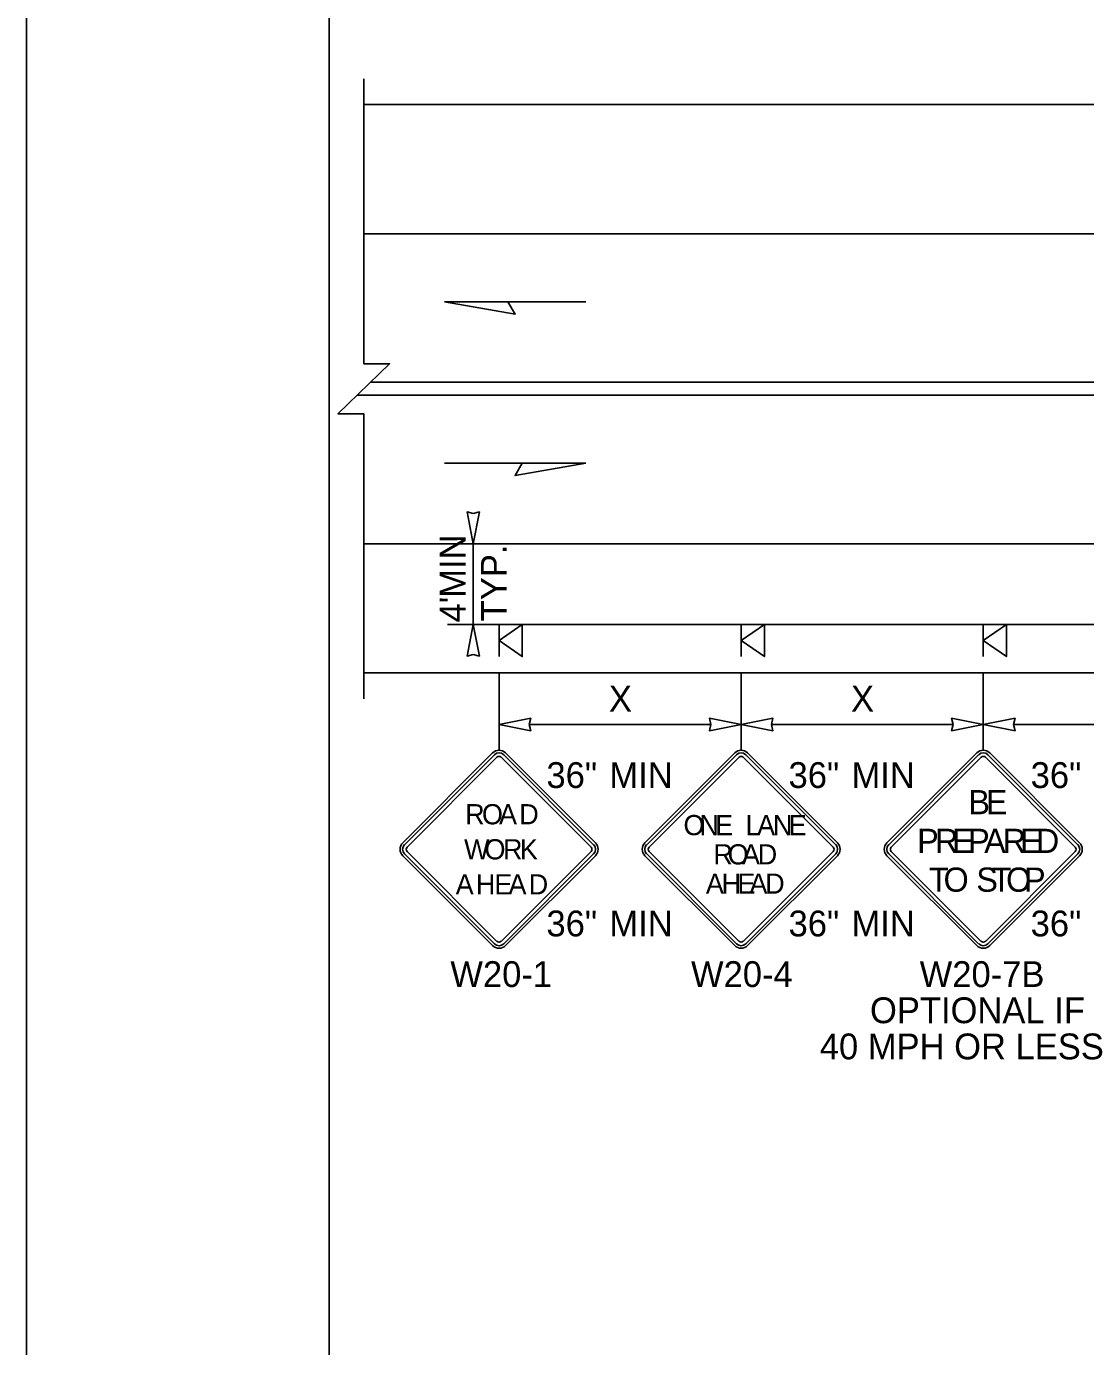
# Model space of a CAD drawing. Extents: x 99998.9 to 100095.7, y 99995 to 100010.7.
# Drawn here: x 100039.062 to 100042.344, y 100003.646 to 100007.734 of the extents above; entities that cross this region are included whole.
import ezdxf

# ---------------------------------------------------------------- set-up
doc = ezdxf.new("R2010")
doc.units = 0
for name, color, linetype in [('RD_ED_ShoulderPavedEdge', 7, 'Continuous'), ('RD_MK_LineDblYellowCenter', 7, 'Continuous'), ('RD_MK_LineEdgeWhite', 7, 'Continuous'), ('SH_GI_PlotLimits', 7, 'Continuous'), ('SH_GI_SheetBorder', 7, 'Continuous'), ('TR_SN_ConstructionSigns', 7, 'Continuous'), ('TR_WZ_PortableSignMountBlk-Org', 7, 'Continuous'), ('TR_WZ_WorkZoneDetails', 7, 'Continuous'), ('TR_WZ_WorkZoneTextCurrent', 7, 'Continuous')]:
    doc.layers.add(name, color=color, linetype=linetype)

msp = doc.modelspace()

# ---------------------------------------------------------------- linework, layer by layer
at = {"layer": 'RD_ED_ShoulderPavedEdge'}
for p, q in [((100040.1076, 100007.4923), (100055.6424, 100007.4923)), ((100040.1076, 100005.7323), (100055.6424, 100005.7323))]:
    msp.add_line(p, q, dxfattribs=at)
at = {"layer": 'RD_MK_LineDblYellowCenter'}
for p, q in [((100040.1282, 100006.6323), (100043.4767, 100006.6323)), ((100040.0869, 100006.5923), (100043.4767, 100006.5923))]:
    msp.add_line(p, q, dxfattribs=at)
at = {"layer": 'RD_MK_LineEdgeWhite'}
for p, q in [((100040.1076, 100007.0923), (100055.6424, 100007.0923)), ((100040.1076, 100006.1323), (100055.6424, 100006.1323))]:
    msp.add_line(p, q, dxfattribs=at)
at = {"layer": 'SH_GI_PlotLimits'}
msp.add_lwpolyline([(100039.0625, 99999.6875), (100056.0625, 99999.6875), (100056.0625, 100010.6875), (100039.0625, 100010.6875)], close=True, dxfattribs=at)
at = {"layer": 'SH_GI_SheetBorder'}
msp.add_line((100040, 100010.375), (100040, 100000), dxfattribs=at)
at = {"layer": 'TR_SN_ConstructionSigns'}
for p, q in [((100040.5068, 100005.4841), (100040.2283, 100005.2057)), ((100040.5123, 100005.4786), (100040.2339, 100005.2001)), ((100040.2416, 100005.1924), (100040.52, 100005.4708)), ((100040.5333, 100005.4708), (100040.8117, 100005.1924)), ((100040.8194, 100005.2001), (100040.541, 100005.4786)), ((100040.825, 100005.2057), (100040.5465, 100005.4841)), ((100041.2568, 100005.4841), (100040.9783, 100005.2057)), ((100041.2623, 100005.4786), (100040.9839, 100005.2001)), ((100040.9916, 100005.1924), (100041.27, 100005.4708)), ((100041.2833, 100005.4708), (100041.5617, 100005.1924)), ((100041.5694, 100005.2001), (100041.291, 100005.4786)), ((100041.575, 100005.2057), (100041.2965, 100005.4841)), ((100042.0068, 100005.4841), (100041.7283, 100005.2057)), ((100042.0123, 100005.4786), (100041.7339, 100005.2001)), ((100041.7416, 100005.1924), (100042.02, 100005.4708)), ((100042.0333, 100005.4708), (100042.3117, 100005.1924)), ((100042.3194, 100005.2001), (100042.041, 100005.4786)), ((100042.325, 100005.2057), (100042.0465, 100005.4841)), ((100040.52, 100004.9007), (100040.2416, 100005.1792)), ((100040.8117, 100005.1792), (100040.5333, 100004.9007)), ((100041.27, 100004.9007), (100040.9916, 100005.1792)), ((100041.5617, 100005.1792), (100041.2833, 100004.9007)), ((100042.02, 100004.9007), (100041.7416, 100005.1792)), ((100042.3117, 100005.1792), (100042.0333, 100004.9007)), ((100040.2283, 100005.1659), (100040.5068, 100004.8875)), ((100040.2339, 100005.1714), (100040.5123, 100004.893)), ((100040.541, 100004.893), (100040.8194, 100005.1714)), ((100040.5465, 100004.8875), (100040.825, 100005.1659)), ((100040.9783, 100005.1659), (100041.2568, 100004.8875)), ((100040.9839, 100005.1714), (100041.2623, 100004.893)), ((100041.291, 100004.893), (100041.5694, 100005.1714)), ((100041.2965, 100004.8875), (100041.575, 100005.1659)), ((100041.7283, 100005.1659), (100042.0068, 100004.8875)), ((100041.7339, 100005.1714), (100042.0123, 100004.893)), ((100042.041, 100004.893), (100042.3194, 100005.1714)), ((100042.0465, 100004.8875), (100042.325, 100005.1659))]:
    msp.add_line(p, q, dxfattribs=at)
for centre, radius, start, end in [((100040.5267, 100005.4642), 0.0281, 45, 135), ((100040.5267, 100005.4642), 0.0203, 45, 135), ((100040.5267, 100005.4642), 0.00937, 45, 135), ((100041.2767, 100005.4642), 0.0281, 45, 135), ((100041.2767, 100005.4642), 0.0203, 45, 135), ((100041.2767, 100005.4642), 0.00937, 45, 135), ((100042.0267, 100005.4642), 0.0281, 45, 135), ((100042.0267, 100005.4642), 0.0203, 45, 135), ((100042.0267, 100005.4642), 0.00937, 45, 135), ((100040.2482, 100005.1858), 0.0281, 135, 225), ((100040.2482, 100005.1858), 0.0203, 135, 225), ((100040.2482, 100005.1858), 0.00937, 135, 225), ((100040.8051, 100005.1858), 0.00937, 315, 45), ((100040.8051, 100005.1858), 0.0203, 315, 45), ((100040.8051, 100005.1858), 0.0281, 315, 45), ((100040.9982, 100005.1858), 0.0281, 135, 225), ((100040.9982, 100005.1858), 0.0203, 135, 225), ((100040.9982, 100005.1858), 0.00937, 135, 225), ((100041.5551, 100005.1858), 0.00937, 315, 45), ((100041.5551, 100005.1858), 0.0203, 315, 45), ((100041.5551, 100005.1858), 0.0281, 315, 45), ((100041.7482, 100005.1858), 0.0281, 135, 225), ((100041.7482, 100005.1858), 0.0203, 135, 225), ((100041.7482, 100005.1858), 0.00937, 135, 225), ((100042.3051, 100005.1858), 0.00937, 315, 45), ((100042.3051, 100005.1858), 0.0203, 315, 45), ((100042.3051, 100005.1858), 0.0281, 315, 45), ((100040.5267, 100004.9074), 0.0203, 225, 315), ((100040.5267, 100004.9074), 0.00937, 225, 315), ((100041.2767, 100004.9074), 0.0203, 225, 315), ((100041.2767, 100004.9074), 0.00937, 225, 315), ((100042.0267, 100004.9074), 0.0203, 225, 315), ((100042.0267, 100004.9074), 0.00937, 225, 315), ((100040.5267, 100004.9074), 0.0281, 225, 315), ((100041.2767, 100004.9074), 0.0281, 225, 315), ((100042.0267, 100004.9074), 0.0281, 225, 315)]:
    msp.add_arc(centre, radius, start, end, dxfattribs=at)
at = {"layer": 'TR_WZ_PortableSignMountBlk-Org'}
for p, q in [((100040.5267, 100005.7824), (100040.5267, 100005.8824)), ((100041.2767, 100005.7824), (100041.2767, 100005.8824)), ((100042.0267, 100005.7824), (100042.0267, 100005.8824))]:
    msp.add_line(p, q, dxfattribs=at)
for points in [[(100040.5267, 100005.8323), (100040.5985, 100005.8824), (100040.5985, 100005.7824)], [(100041.2767, 100005.8323), (100041.3485, 100005.8824), (100041.3485, 100005.7824)], [(100042.0267, 100005.8323), (100042.0985, 100005.8824), (100042.0985, 100005.7824)]]:
    msp.add_lwpolyline(points, close=True, dxfattribs=at)
at = {"layer": 'TR_WZ_WorkZoneDetails'}
for p, q in [((100040.5541, 100006.8816), (100040.7952, 100006.8816)), ((100040.5987, 100006.3816), (100040.3576, 100006.3816)), ((100040.3667, 100006.1323), (100040.5267, 100006.1323)), ((100040.4467, 100005.8824), (100040.4467, 100006.1323)), ((100040.3667, 100005.8824), (100040.5267, 100005.8824)), ((100040.5267, 100005.8824), (100043.5267, 100005.8824)), ((100040.5267, 100005.7326), (100040.5267, 100005.4923)), ((100041.2767, 100005.7323), (100041.2767, 100005.4923)), ((100042.0267, 100005.7323), (100042.0267, 100005.4923)), ((100041.1829, 100005.5723), (100040.6204, 100005.5723)), ((100041.9329, 100005.5723), (100041.3704, 100005.5723)), ((100042.6829, 100005.5723), (100042.1204, 100005.5723))]:
    msp.add_line(p, q, dxfattribs=at)
msp.add_lwpolyline([(100040.1076, 100005.6523), (100040.1076, 100006.5349), (100040.0275, 100006.5349), (100040.1876, 100006.6898), (100040.1076, 100006.6898), (100040.1076, 100007.5723)], dxfattribs=at)
for points in [[(100040.3576, 100006.8816), (100040.5764, 100006.843), (100040.5541, 100006.8816)], [(100040.7952, 100006.3816), (100040.5764, 100006.343), (100040.5987, 100006.3816)], [(100040.4467, 100006.1323), (100040.4274, 100006.2306), (100040.4467, 100006.2261), (100040.4659, 100006.2306)], [(100040.4467, 100005.8824), (100040.4274, 100005.7841), (100040.4467, 100005.7887), (100040.4659, 100005.7841)], [(100040.5267, 100005.5723), (100040.6249, 100005.5916), (100040.6204, 100005.5723), (100040.6249, 100005.5531)], [(100041.2767, 100005.5723), (100041.1784, 100005.5916), (100041.1829, 100005.5723), (100041.1784, 100005.5531)], [(100041.2767, 100005.5723), (100041.3749, 100005.5916), (100041.3704, 100005.5723), (100041.3749, 100005.5531)], [(100042.0267, 100005.5723), (100041.9284, 100005.5916), (100041.9329, 100005.5723), (100041.9284, 100005.5531)], [(100042.0267, 100005.5723), (100042.1249, 100005.5916), (100042.1204, 100005.5723), (100042.1249, 100005.5531)]]:
    msp.add_lwpolyline(points, close=True, dxfattribs=at)

# ---------------------------------------------------------------- texts
at = {"layer": 'TR_SN_ConstructionSigns'}
for s, p in [('36"', (100040.6734, 100005.3756)), ('MIN', (100040.8684, 100005.3756)), ('36"', (100041.4234, 100005.3756)), ('MIN', (100041.6184, 100005.3756)), ('36"', (100042.1734, 100005.3756)), ('36"', (100040.6734, 100004.916)), ('MIN', (100040.8684, 100004.916)), ('36"', (100041.4234, 100004.916)), ('MIN', (100041.6184, 100004.916)), ('36"', (100042.1734, 100004.916)), ('W20-1', (100040.3757, 100004.7592)), ('W20-4', (100041.1212, 100004.7592)), ('W20-7B', (100041.8296, 100004.7592)), ('OPTIONAL IF', (100041.6757, 100004.6472)), ('40 MPH OR LESS', (100041.5202, 100004.5352))]:
    msp.add_text(s, height=0.08, rotation=360, dxfattribs=at).set_placement(p)
for s, height, p in [('B', 0.075, (100041.9804, 100005.2943)), ('E', 0.075, (100042.0347, 100005.2943)), ('R', 0.0625, (100040.4216, 100005.2631)), ('O', 0.0625, (100040.4737, 100005.2631)), ('A', 0.0625, (100040.5265, 100005.2631)), ('D', 0.0625, (100040.5892, 100005.2631)), ('O', 0.0625, (100041.0979, 100005.2295)), ('N', 0.0625, (100041.1473, 100005.2295)), ('E', 0.0625, (100041.196, 100005.2295)), ('L', 0.0625, (100041.2904, 100005.2295)), ('A', 0.0625, (100041.326, 100005.2295)), ('N', 0.0625, (100041.3748, 100005.2295)), ('E', 0.0625, (100041.4235, 100005.2295)), ('W', 0.0625, (100040.4183, 100005.1545)), ('O', 0.0625, (100040.4816, 100005.1545)), ('R', 0.0625, (100040.5388, 100005.1545)), ('K', 0.0625, (100040.5912, 100005.1545)), ('P', 0.075, (100041.8218, 100005.1743)), ('R', 0.075, (100041.877, 100005.1743)), ('E', 0.075, (100041.9302, 100005.1743)), ('P', 0.075, (100041.9797, 100005.1743)), ('A', 0.075, (100042.0296, 100005.1743)), ('R', 0.075, (100042.0868, 100005.1743)), ('E', 0.075, (100042.1401, 100005.1743)), ('D', 0.075, (100042.1896, 100005.1743)), ('R', 0.0625, (100041.1904, 100005.1389)), ('O', 0.0625, (100041.2348, 100005.1389)), ('A', 0.0625, (100041.2792, 100005.1389)), ('D', 0.0625, (100041.3279, 100005.1389)), ('A', 0.0625, (100040.3923, 100005.046)), ('H', 0.0625, (100040.4548, 100005.046)), ('E', 0.0625, (100040.5123, 100005.046)), ('A', 0.0625, (100040.556, 100005.046)), ('D', 0.0625, (100040.6185, 100005.046)), ('A', 0.0625, (100041.1673, 100005.0483)), ('H', 0.0625, (100041.216, 100005.0483)), ('E', 0.0625, (100041.2648, 100005.0483)), ('A', 0.0625, (100041.3023, 100005.0483)), ('D', 0.0625, (100041.351, 100005.0483)), ('T', 0.075, (100041.8584, 100005.0543)), ('O', 0.075, (100041.9035, 100005.0543)), ('S', 0.075, (100042.005, 100005.0543)), ('T', 0.075, (100042.0521, 100005.0543)), ('O', 0.075, (100042.0972, 100005.0543)), ('P', 0.075, (100042.1529, 100005.0543))]:
    msp.add_text(s, height=height, dxfattribs=at).set_placement(p)
at = {"layer": 'TR_WZ_WorkZoneTextCurrent'}
for s, rotation, p in [('MIN', 90, (100040.4227, 100005.9648)), ('TYP.', 90, (100040.5507, 100005.892)), ("4'", 90, (100040.4227, 100005.8883)), ('X', 360, (100040.8669, 100005.6123)), ('X', 360, (100041.6169, 100005.6123))]:
    msp.add_text(s, height=0.08, rotation=rotation, dxfattribs=at).set_placement(p)

doc.saveas('drawing.dxf')
